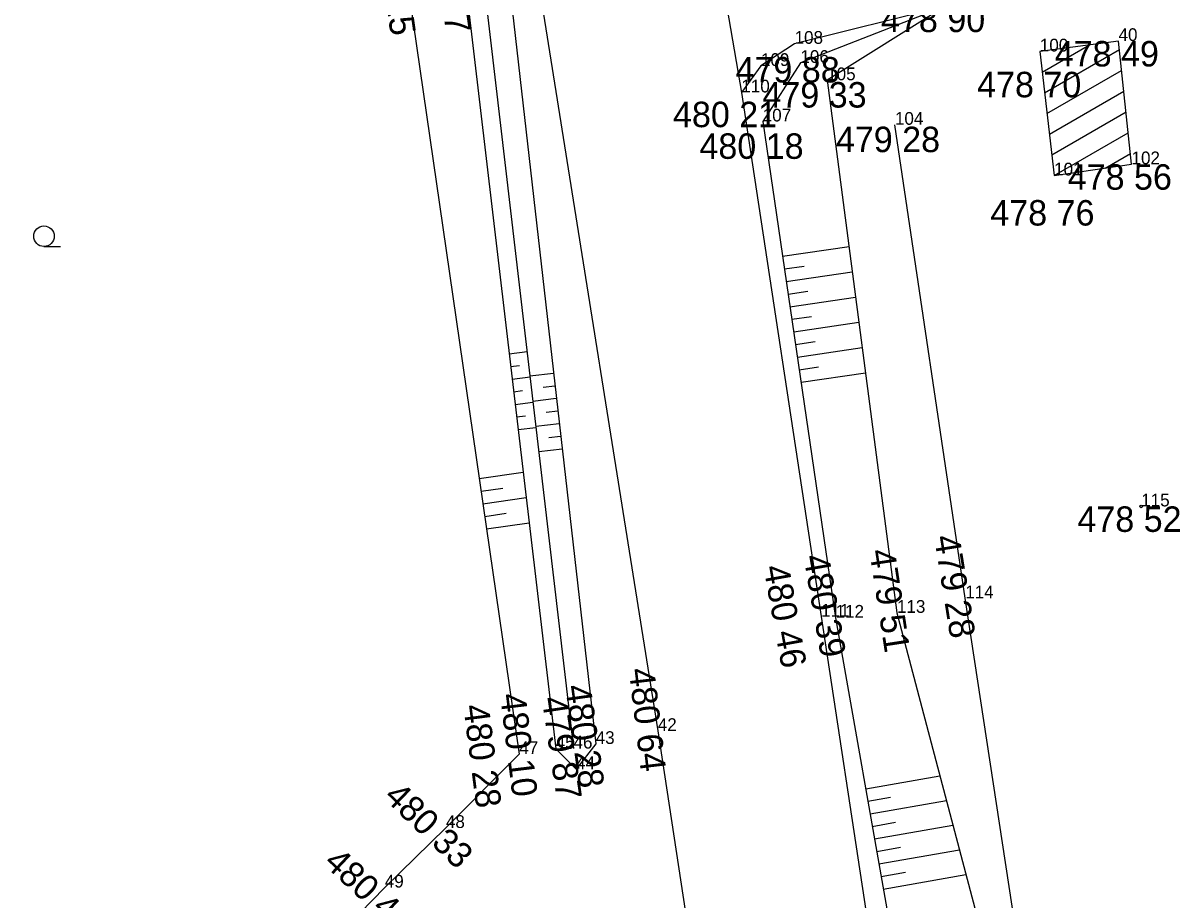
# Model space of a CAD drawing. Extents: x -559180 to -551373, y -1076947 to -1072071.
# Drawn here: x -553763.99 to -553718.57, y -1076010.35 to -1075975.92 of the extents above; entities that cross this region are included whole.
import ezdxf

# ---------------------------------------------------------------- set-up
doc = ezdxf.new("R2010")
doc.units = 0
for name, color, linetype in [('12_PLOTY', 7, 'Continuous'), ('14_BUDOVY', 7, 'Continuous'), ('17_KOMUNIKACE', 7, 'Continuous'), ('1_VODA_ZN', 7, 'Continuous'), ('26_SRAFY', 7, 'Continuous'), ('27_HRANA_PATA', 7, 'Continuous'), ('32', 7, 'Continuous'), ('3_BODY', 7, 'Continuous'), ('45_ZN_KULTURY', 7, 'Continuous'), ('6_VYSKY', 7, 'Continuous')]:
    doc.layers.add(name, color=color, linetype=linetype)

# ---------------------------------------------------------------- blocks, each defined once
blk = doc.blocks.new('POINT_DISPLAY')
blk.add_line((0, 0), (0, 0))
blk = doc.blocks.new('ZAHRAD')
at = {"layer": '45_ZN_KULTURY'}
blk.add_line((0, 0), (0.65, 0.003), dxfattribs=at)
blk.add_circle((0, 0.403), 0.403, dxfattribs=at)
blk = doc.blocks.new('T')
at = {"layer": '6_VYSKY'}
blk.add_circle((0, 0), 0.05, dxfattribs=at)

msp = doc.modelspace()

# ---------------------------------------------------------------- linework, layer by layer
at = {"layer": '12_PLOTY'}
for p, q in [((-553748.81, -1075974.99), (-553744.51, -1076004.63)), ((-553727, -1075998.51), (-553729.76, -1075979.91)), ((-553724.63, -1076014.04), (-553727, -1075998.51)), ((-553744.51, -1076004.63), (-553747.39, -1076007.53)), ((-553747.39, -1076007.53), (-553749.79, -1076009.87)), ((-553749.79, -1076009.87), (-553763.99, -1076024.33))]:
    msp.add_line(p, q, dxfattribs=at)
at = {"layer": '14_BUDOVY'}
for p, q in [((-553720.98, -1075976.62), (-553724.07, -1075977.03)), ((-553720.47, -1075981.46), (-553720.98, -1075976.62)), ((-553724.07, -1075977.03), (-553723.51, -1075981.9)), ((-553723.51, -1075981.9), (-553720.47, -1075981.46))]:
    msp.add_line(p, q, dxfattribs=at)
at = {"layer": '17_KOMUNIKACE'}
for p, q in [((-553736.89, -1075972.14), (-553735.79, -1075978.64)), ((-553743.79, -1075974.11), (-553739.07, -1076003.72)), ((-553727.8, -1075975.27), (-553733.7, -1075976.73)), ((-553733.7, -1075976.73), (-553735.02, -1075977.6)), ((-553735.02, -1075977.6), (-553735.79, -1075978.64)), ((-553735.79, -1075978.64), (-553732.66, -1075999.23)), ((-553732.66, -1075999.23), (-553728.13, -1076029.02)), ((-553739.07, -1076003.72), (-553733.75, -1076038.56))]:
    msp.add_line(p, q, dxfattribs=at)
at = {"layer": '26_SRAFY'}
for p, q in [((-553731.563, -1075984.707), (-553734.171, -1075985.09)), ((-553733.318, -1075985.47), (-553734.098, -1075985.584)), ((-553731.433, -1075985.699), (-553734.026, -1075986.079)), ((-553733.178, -1075986.46), (-553733.953, -1075986.574)), ((-553731.303, -1075986.69), (-553733.88, -1075987.068)), ((-553733.037, -1075987.45), (-553733.808, -1075987.563)), ((-553731.173, -1075987.682), (-553733.735, -1075988.058)), ((-553732.896, -1075988.44), (-553733.663, -1075988.553)), ((-553744.204, -1075988.834), (-553744.907, -1075988.917)), ((-553731.043, -1075988.674), (-553733.59, -1075989.047)), ((-553744.497, -1075989.372), (-553744.849, -1075989.414)), ((-553744.087, -1075989.828), (-553744.79, -1075989.91)), ((-553744.094, -1075989.766), (-553743.168, -1075989.661)), ((-553732.756, -1075989.43), (-553733.518, -1075989.542)), ((-553730.913, -1075989.665), (-553733.445, -1075990.037)), ((-553743.574, -1075990.21), (-553743.112, -1075990.158)), ((-553744.38, -1075990.366), (-553744.732, -1075990.407)), ((-553743.978, -1075990.76), (-553743.055, -1075990.654)), ((-553743.971, -1075990.821), (-553744.673, -1075990.904)), ((-553743.459, -1075991.204), (-553742.998, -1075991.151)), ((-553744.264, -1075991.359), (-553744.615, -1075991.4)), ((-553743.862, -1075991.753), (-553742.942, -1075991.648)), ((-553743.855, -1075991.814), (-553744.556, -1075991.897)), ((-553743.345, -1075992.197), (-553742.885, -1075992.145)), ((-553743.746, -1075992.746), (-553742.829, -1075992.642)), ((-553744.359, -1075993.569), (-553746.078, -1075993.818)), ((-553745.154, -1075994.19), (-553746.007, -1075994.313)), ((-553744.242, -1075994.563), (-553745.935, -1075994.808)), ((-553745.023, -1075995.181), (-553745.863, -1075995.303)), ((-553744.125, -1075995.556), (-553745.791, -1075995.798)), ((-553727.993, -1076005.49), (-553730.908, -1076006.002)), ((-553729.934, -1076006.339), (-553730.821, -1076006.494)), ((-553727.738, -1076006.46), (-553730.735, -1076006.987)), ((-553729.737, -1076007.319), (-553730.648, -1076007.479)), ((-553727.482, -1076007.431), (-553730.562, -1076007.972)), ((-553729.539, -1076008.3), (-553730.475, -1076008.464)), ((-553727.227, -1076008.401), (-553730.389, -1076008.957)), ((-553729.341, -1076009.28), (-553730.302, -1076009.449)), ((-553726.971, -1076009.372), (-553730.216, -1076009.942))]:
    msp.add_line(p, q, dxfattribs=at)
at = {"layer": '27_HRANA_PATA'}
for p, q in [((-553744.93, -1075974.18), (-553741.51, -1076004.23)), ((-553746.59, -1075974.64), (-553743.08, -1076004.42)), ((-553745.89, -1075974.43), (-553742.38, -1076004.41)), ((-553727.8, -1075975.27), (-553733.47, -1075977.48)), ((-553727.8, -1075975.27), (-553732.42, -1075978.16)), ((-553733.47, -1075977.48), (-553734.95, -1075979.78)), ((-553732.42, -1075978.16), (-553729.68, -1075999.08)), ((-553734.95, -1075979.78), (-553732.09, -1075999.27)), ((-553732.09, -1075999.27), (-553728.99, -1076016.92)), ((-553729.68, -1075999.08), (-553725.05, -1076016.67)), ((-553741.51, -1076004.23), (-553742.28, -1076005.22)), ((-553742.28, -1076005.22), (-553743.08, -1076004.42))]:
    msp.add_line(p, q, dxfattribs=at)
at = {"layer": '32'}
for p, q in [((-553723.977, -1075977.842), (-553722.122, -1075976.772)), ((-553723.883, -1075978.654), (-553720.944, -1075976.958)), ((-553723.79, -1075979.466), (-553720.858, -1075977.774)), ((-553723.696, -1075980.278), (-553720.772, -1075978.59)), ((-553723.603, -1075981.091), (-553720.686, -1075979.407)), ((-553723.503, -1075981.899), (-553720.6, -1075980.223)), ((-553721.502, -1075981.609), (-553720.514, -1075981.039))]:
    msp.add_line(p, q, dxfattribs=at)

# ---------------------------------------------------------------- block references
at = {"layer": '1_VODA_ZN'}
for p in [(-553720.98, -1075976.62), (-553733.7, -1075976.73), (-553724.07, -1075977.03), (-553733.47, -1075977.48), (-553735.02, -1075977.6), (-553732.42, -1075978.16), (-553735.79, -1075978.64), (-553734.95, -1075979.78), (-553729.76, -1075979.91), (-553720.47, -1075981.46), (-553723.51, -1075981.9), (-553720.09, -1075994.9), (-553727, -1075998.51), (-553732.66, -1075999.23), (-553732.09, -1075999.27), (-553729.68, -1075999.08), (-553739.07, -1076003.72), (-553741.51, -1076004.23), (-553744.51, -1076004.63), (-553743.08, -1076004.42), (-553742.38, -1076004.41), (-553742.28, -1076005.22), (-553747.39, -1076007.53), (-553749.79, -1076009.87)]:
    msp.add_blockref('POINT_DISPLAY', p, dxfattribs=at)
at = {"layer": '32'}
msp.add_blockref('POINT_DISPLAY', (-553724.07, -1075977.03), dxfattribs=at)
at = {"layer": '45_ZN_KULTURY'}
msp.add_blockref('ZAHRAD', (-553763.172, -1075984.69), dxfattribs=at)
at = {"layer": '6_VYSKY'}
msp.add_blockref('T', (-553720.09, -1075994.9), dxfattribs=at)
msp.add_blockref('T', (-553720.09, -1075994.9), dxfattribs=at)

# ---------------------------------------------------------------- texts
at = {"layer": '3_BODY'}
for s, p in [('40', (-553720.98, -1075976.62)), ('108', (-553733.7, -1075976.73)), ('100', (-553724.07, -1075977.03)), ('109', (-553735.02, -1075977.6)), ('106', (-553733.47, -1075977.48)), ('105', (-553732.42, -1075978.16)), ('110', (-553735.79, -1075978.64)), ('107', (-553734.95, -1075979.78)), ('104', (-553729.76, -1075979.91)), ('102', (-553720.47, -1075981.46)), ('101', (-553723.51, -1075981.9)), ('115', (-553720.09, -1075994.9)), ('114', (-553727, -1075998.51)), ('111', (-553732.66, -1075999.23)), ('112', (-553732.09, -1075999.27)), ('113', (-553729.68, -1075999.08)), ('42', (-553739.07, -1076003.72)), ('46', (-553742.38, -1076004.41)), ('43', (-553741.51, -1076004.23)), ('47', (-553744.51, -1076004.63)), ('45', (-553743.08, -1076004.42)), ('44', (-553742.28, -1076005.22)), ('48', (-553747.39, -1076007.53)), ('49', (-553749.79, -1076009.87))]:
    msp.add_text(s, height=0.5, dxfattribs=at).set_placement(p)
at = {"layer": '6_VYSKY'}
for s, rotation, p in [('480 15', 278.0414, (-553750.121, -1075972.404)), ('480 07', 278.3637, (-553747.968, -1075972.319)), ('479 28', 279.1159, (-553728.225, -1075996.096)), ('479 51', 278.6864, (-553730.767, -1075996.644)), ('480 39', 279.8658, (-553733.353, -1075996.865)), ('480 46', 280.243, (-553734.925, -1075997.282)), ('480 64', 276.6967, (-553740.212, -1076001.296)), ('480 28', 277.9199, (-553742.71, -1076001.96)), ('480 10', 276.9125, (-553745.265, -1076002.293)), ('479 87', 278.4584, (-553743.631, -1076002.431)), ('480 28', 277.2904, (-553746.71, -1076002.732)), ('480 33', 315.9663, (-553749.87, -1076006.352)), ('480 40', 316.8183, (-553752.229, -1076008.948))]:
    msp.add_text(s, height=1, rotation=rotation, dxfattribs=at).set_placement(p)
for s, p in [('478 90', (-553730.305, -1075976.27)), ('478 49', (-553723.485, -1075977.62)), ('479 88', (-553736.019, -1075978.249)), ('478 70', (-553726.533, -1075978.83)), ('479 33', (-553734.962, -1075979.234)), ('480 21', (-553738.474, -1075980.004)), ('480 18', (-553737.436, -1075981.248)), ('479 28', (-553732.078, -1075980.985)), ('478 56', (-553722.975, -1075982.46)), ('478 76', (-553726.015, -1075983.868)), ('478 52', (-553722.595, -1075995.9))]:
    msp.add_text(s, height=1, dxfattribs=at).set_placement(p)

doc.saveas('drawing.dxf')
